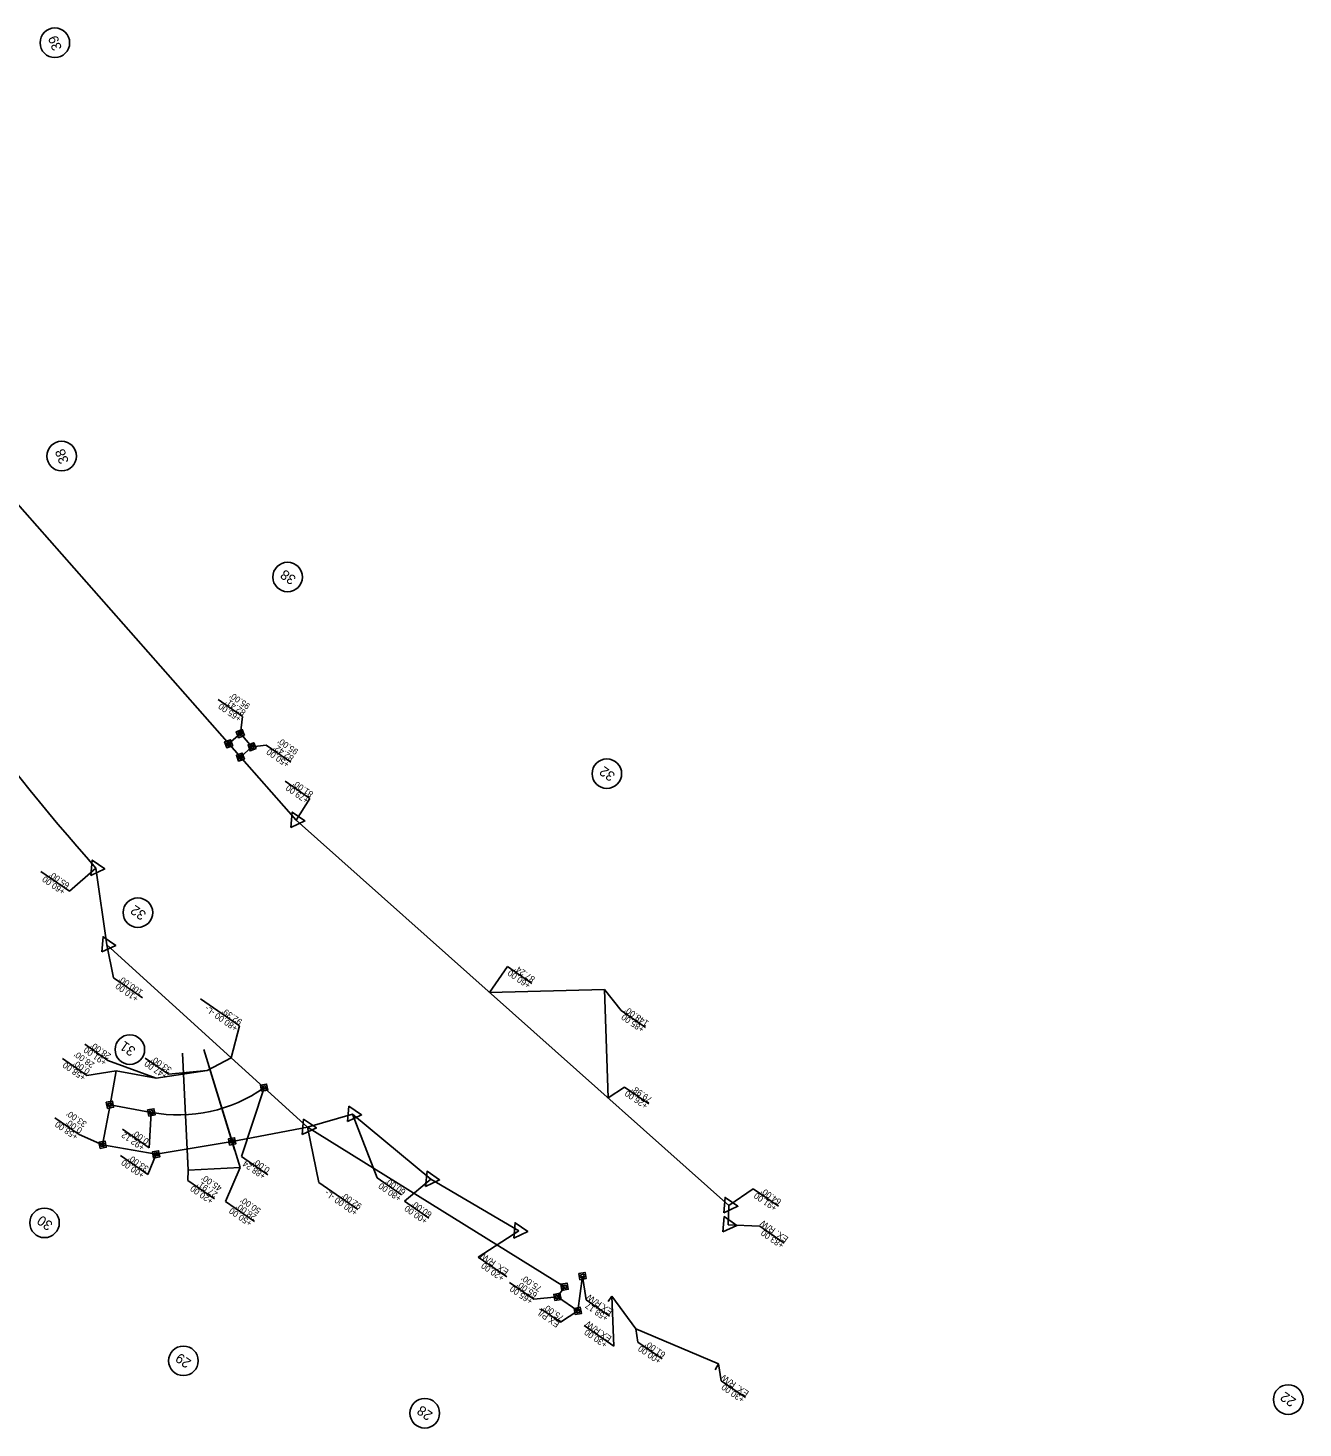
# Model space of a CAD drawing. Extents: x 474184 to 481900, y 489262 to 505659.
# Drawn here: x 478811 to 479844, y 493622 to 494757 of the extents above; entities that cross this region are included whole.
import ezdxf

# ---------------------------------------------------------------- set-up
doc = ezdxf.new("R2010")
doc.units = 0
for name, color, linetype in [('Prop Drainage Structure Drop Inlet Grate 2 Narrow Slots and Sag Grates 840 24 CELL', 7, 'Continuous'), ('Prop Drainage Structure Drop Inlet Grate 2 Wide Slots and Sag Grates 840 22 CELL', 7, 'Continuous'), ('Prop Drainage Structure Outlet Berm Ditch 850 10 CELL', 7, 'Continuous'), ('Prop Drainage Structure Outlet Berm Ditch 850 10 Label', 7, 'Continuous'), ('Prop Drainage Structure Pipe CSP 15in', 7, 'Continuous'), ('Prop Drainage Structure Pipe RCP 18in Class IV', 7, 'Continuous'), ('Prop Drainage Structure Pipe RCP 18in Class IV Label', 7, 'Continuous'), ('Prop Drainage Structure Pipe Side Drain 15in Label', 7, 'Continuous'), ('Prop Drainage Structure Pipe Stub Out CELL', 7, 'Continuous'), ('Prop Drainage Structure Plot Symbol 50 Scale', 7, 'Continuous'), ('Prop Earthen Structure Base Ditch Lateral Detail Label', 7, 'Continuous'), ('Prop Earthen Structure False Sump CELL', 7, 'Continuous'), ('Prop Earthen Structure False Sump Label', 7, 'Continuous'), ('Sheet Block Title CELL', 7, 'Continuous')]:
    doc.layers.add(name, color=color, linetype=linetype)

msp = doc.modelspace()

# ---------------------------------------------------------------- linework, layer by layer
at = {"layer": 'Prop Drainage Structure Drop Inlet Grate 2 Narrow Slots and Sag Grates 840 24 CELL'}
for p, q in [((479278, 493977.6), (479184.8, 493975.3)), ((479281, 493889.7), (479278, 493977.6))]:
    msp.add_line(p, q, dxfattribs=at)
at = {"layer": 'Prop Drainage Structure Drop Inlet Grate 2 Wide Slots and Sag Grates 840 22 CELL'}
for p, q in [((478871.1, 493851.7), (478877.2, 493884.2)), ((478877.2, 493884.2), (478910.7, 493877.9)), ((479037.3, 493866), (478976.2, 493854.4)), ((478976.2, 493854.4), (478914.6, 493844)), ((478914.6, 493844), (478871.1, 493851.7)), ((479281.1, 493724.5), (479284.1, 493729)), ((479367.7, 493669.3), (479370.6, 493674.1))]:
    msp.add_line(p, q, dxfattribs=at)
msp.add_arc((478932.7, 493995.9), 120, 259.4473, 305.3419, dxfattribs=at)
at = {"layer": 'Prop Drainage Structure Outlet Berm Ditch 850 10 CELL'}
for p, q in [((479199.4, 493996.2), (479219.1, 493982.6)), ((479291.5, 493960.6), (479311.3, 493946.9)), ((479294.4, 493898.5), (479314.1, 493884.9))]:
    msp.add_line(p, q, dxfattribs=at)
for points in [[(479184.8, 493975.3), (479199.4, 493996.2)], [(479291.5, 493960.6), (479278, 493977.6)], [(479294.4, 493898.5), (479281, 493889.7)]]:
    msp.add_lwpolyline(points, dxfattribs=at)
at = {"layer": 'Prop Drainage Structure Outlet Berm Ditch 850 10 Label'}
for p, q in [((478982.9, 494185.2), (478973.4, 494176.9)), ((478992.3, 494174.5), (478982.9, 494185.2)), ((478982.9, 494166.1), (478992.3, 494174.5)), ((479245.7, 493736.6), (479037.3, 493866)), ((479256.5, 493717), (479260.3, 493745.2)), ((479240, 493728.4), (479245.7, 493736.6)), ((479240, 493728.4), (479256.5, 493717))]:
    msp.add_line(p, q, dxfattribs=at)
at = {"layer": 'Prop Drainage Structure Pipe CSP 15in'}
for p, q in [((478832.5, 494745.5), (478832.5, 494745.5)), ((478838, 494410.3), (478838, 494410.3)), ((479021.2, 494312.2), (479021.2, 494312.2)), ((479280, 494152.7), (479280, 494152.7)), ((478899.8, 494040), (478899.8, 494040)), ((478893.3, 493928.9), (478893.3, 493928.9)), ((478824.1, 493788.4), (478824.1, 493788.4)), ((478936.7, 493676.5), (478936.7, 493676.5)), ((479832.4, 493645.1), (479832.4, 493645.1)), ((479132.4, 493634), (479132.4, 493634))]:
    msp.add_line(p, q, dxfattribs=at)
for centre in [(478832.5, 494745.5), (478838, 494410.3), (479021.2, 494312.2), (479280, 494152.7), (478899.8, 494040), (478893.3, 493928.9), (478824.1, 493788.4), (478936.7, 493676.5), (479832.4, 493645.1), (479132.4, 493634)]:
    msp.add_circle(centre, 12, dxfattribs=at)
at = {"layer": 'Prop Drainage Structure Pipe RCP 18in Class IV'}
for p, q in [((478982.9, 494185.2), (478982.9, 494185.2)), ((478973.4, 494176.9), (478973.4, 494176.9)), ((478992.3, 494174.5), (478992.3, 494174.5)), ((478982.9, 494166.1), (478982.9, 494166.1)), ((479028, 494115), (479028, 494115)), ((478865.8, 494076), (478865.8, 494076)), ((478874.6, 494014), (478874.6, 494014)), ((479002.1, 493898), (479002.1, 493898)), ((478877.2, 493884.2), (478877.2, 493884.2)), ((478910.7, 493877.9), (478910.7, 493877.9)), ((479037.3, 493866), (479037.3, 493866)), ((479073.9, 493876.5), (479073.9, 493876.5)), ((478976.2, 493854.4), (478976.2, 493854.4)), ((478871.1, 493851.7), (478871.1, 493851.7)), ((478914.6, 493844), (478914.6, 493844)), ((479137.2, 493823.8), (479137.2, 493823.8)), ((479379, 493802.5), (479379, 493802.5)), ((479378.3, 493786.9), (479378.3, 493786.9)), ((479208.7, 493782), (479208.7, 493782)), ((479260.3, 493745.2), (479260.3, 493745.2)), ((479245.7, 493736.6), (479245.7, 493736.6)), ((479240, 493728.4), (479240, 493728.4)), ((479256.5, 493717), (479256.5, 493717))]:
    msp.add_line(p, q, dxfattribs=at)
for points in [[(479023.9, 494109.1), (479024.9, 494121.5), (479035.2, 494114.4)], [(478861.7, 494070.1), (478862.8, 494082.6), (478873, 494075.4)], [(478870.5, 494008.1), (478871.6, 494020.5), (478881.8, 494013.4)], [(479069.8, 493870.5), (479070.9, 493883), (479081.1, 493875.9)], [(479033.1, 493860.1), (479034.2, 493872.5), (479044.5, 493865.4)], [(479133.1, 493817.9), (479134.2, 493830.3), (479144.4, 493823.2)], [(479374.9, 493796.6), (479375.9, 493809), (479386.2, 493801.9)], [(479204.6, 493776.1), (479205.6, 493788.5), (479215.9, 493781.4)], [(479374.1, 493781), (479375.2, 493793.5), (479385.4, 493786.3)]]:
    msp.add_lwpolyline(points, close=True, dxfattribs=at)
at = {"layer": 'Prop Drainage Structure Pipe RCP 18in Class IV Label'}
for points in [[(478986.2, 494183.7), (478981.4, 494181.9), (478979.6, 494186.7), (478984.4, 494188.5)], [(478984.5, 494184.5), (478982.1, 494183.6), (478981.3, 494186), (478983.6, 494186.9)], [(478976.7, 494175.4), (478971.9, 494173.7), (478970.1, 494178.4), (478974.9, 494180.2)], [(478975, 494176.2), (478972.7, 494175.3), (478971.8, 494177.7), (478974.2, 494178.6)], [(478995.6, 494173), (478990.8, 494171.2), (478989.1, 494176), (478993.8, 494177.8)], [(478994, 494173.7), (478991.6, 494172.8), (478990.7, 494175.2), (478993.1, 494176.1)], [(478986.2, 494164.6), (478981.4, 494162.9), (478979.7, 494167.6), (478984.4, 494169.4)], [(478984.6, 494165.4), (478982.2, 494164.5), (478981.3, 494166.9), (478983.7, 494167.8)], [(479000, 493895.1), (478999.1, 493900.1), (479004.1, 493901), (479005.1, 493896)], [(479001.1, 493896.5), (479000.6, 493899), (479003.1, 493899.5), (479003.6, 493897)], [(478875.1, 493881.2), (478874.2, 493886.2), (478879.2, 493887.1), (478880.1, 493882.1)], [(478876.1, 493882.7), (478875.7, 493885.2), (478878.2, 493885.7), (478878.6, 493883.2)], [(478908.7, 493875), (478907.7, 493880), (478912.8, 493880.9), (478913.7, 493875.9)], [(478909.7, 493876.4), (478909.2, 493879), (478911.7, 493879.4), (478912.2, 493876.9)], [(478869.1, 493848.8), (478868.2, 493853.8), (478873.2, 493854.7), (478874.1, 493849.7)], [(478974.1, 493851.5), (478973.2, 493856.5), (478978.2, 493857.4), (478979.1, 493852.4)], [(478975.1, 493852.9), (478974.7, 493855.5), (478977.2, 493855.9), (478977.6, 493853.4)], [(478870.1, 493850.3), (478869.6, 493852.8), (478872.1, 493853.2), (478872.6, 493850.7)], [(478912.5, 493841), (478911.6, 493846), (478916.6, 493846.9), (478917.5, 493841.9)], [(478913.6, 493842.5), (478913.1, 493845), (478915.6, 493845.4), (478916.1, 493842.9)], [(479258.2, 493742.3), (479257.3, 493747.3), (479262.3, 493748.2), (479263.2, 493743.2)], [(479259.2, 493743.7), (479258.8, 493746.2), (479261.3, 493746.7), (479261.7, 493744.2)], [(479237.9, 493725.4), (479237, 493730.4), (479242, 493731.3), (479242.9, 493726.3)], [(479238.9, 493726.9), (479238.5, 493729.4), (479241, 493729.8), (479241.5, 493727.3)], [(479243.6, 493733.6), (479242.7, 493738.6), (479247.7, 493739.5), (479248.7, 493734.5)], [(479244.7, 493735.1), (479244.2, 493737.6), (479246.7, 493738), (479247.2, 493735.5)], [(479254.4, 493714), (479253.5, 493719), (479258.5, 493719.9), (479259.5, 493714.9)], [(479255.5, 493715.5), (479255, 493718), (479257.5, 493718.4), (479258, 493715.9)]]:
    msp.add_lwpolyline(points, close=True, dxfattribs=at)
at = {"layer": 'Prop Drainage Structure Pipe Side Drain 15in Label'}
for p, q in [((479379, 493802.5), (479028, 494115)), ((478874.6, 494014), (478865.8, 494076)), ((479037.3, 493866), (478874.6, 494014)), ((479378.3, 493786.9), (479379, 493802.5))]:
    msp.add_line(p, q, dxfattribs=at)
for points in [[(479028, 494115), (478737.9, 494444.3)], [(479208.7, 493782), (479137.2, 493823.8), (479073.9, 493876.5), (479037.3, 493866)]]:
    msp.add_lwpolyline(points, dxfattribs=at)
msp.add_arc((480454.8, 495471.8), 2115, 200.8785, 221.2966, dxfattribs=at)
at = {"layer": 'Prop Drainage Structure Pipe Stub Out CELL'}
for p, q in [((478877.2, 493884.2), (478882.3, 493911.7)), ((478914.7, 493905.7), (478882.3, 493911.7)), ((478956.1, 493912.1), (478914.7, 493905.7)), ((478975.4, 493922.3), (478956.1, 493912.1)), ((478982.6, 493833.4), (478976.2, 493854.4)), ((478940.6, 493831.1), (478939.8, 493848.2)), ((478982.6, 493833.4), (478940.6, 493831.1)), ((479303.5, 493702.5), (479284.1, 493729)), ((479370.6, 493674.1), (479303.5, 493702.5))]:
    msp.add_line(p, q, dxfattribs=at)
at = {"layer": 'Prop Drainage Structure Plot Symbol 50 Scale'}
for p, q in [((479019.2, 494146.6), (479039.2, 494132.7)), ((479039.2, 494132.7), (479028, 494115)), ((478821.2, 494073.4), (478844.4, 494057.3)), ((478880, 493987.1), (478903.6, 493970.8)), ((479046.6, 493821.2), (479078.2, 493799.2)), ((479093.7, 493824.8), (479113.5, 493811.1)), ((479398.7, 493816.1), (479419.2, 493801.9)), ((479116, 493805.9), (479135.8, 493792.2)), ((479175.8, 493760.7), (479208.7, 493782)), ((479403.9, 493785.7), (479423.7, 493772)), ((479175.8, 493760.7), (479199, 493744.6))]:
    msp.add_line(p, q, dxfattribs=at)
for points in [[(478844.4, 494057.3), (478865.8, 494076)], [(478880, 493987.1), (478874.6, 494014)], [(479046.6, 493821.2), (479037.3, 493866)], [(479093.7, 493824.8), (479073.9, 493876.5)], [(479116, 493805.9), (479137.2, 493823.8)], [(479398.7, 493816.1), (479379, 493802.5)], [(479403.9, 493785.7), (479378.3, 493786.9)]]:
    msp.add_lwpolyline(points, dxfattribs=at)
at = {"layer": 'Prop Earthen Structure Base Ditch Lateral Detail Label'}
for p, q in [((478964.9, 494212.8), (478984.7, 494199.1)), ((478984.7, 494199.1), (478982.9, 494185.2)), ((479003.9, 494175.8), (478992.3, 494174.5)), ((479003.9, 494175.8), (479023.7, 494162.1)), ((479201.1, 493740.1), (479220.9, 493726.4)), ((479226.6, 493718.8), (479242.5, 493707.8)), ((479263.2, 493725.9), (479282.1, 493712.8))]:
    msp.add_line(p, q, dxfattribs=at)
for points in [[(479263.2, 493725.9), (479260.3, 493745.2)], [(479220.9, 493726.4), (479240, 493728.4)], [(479242.5, 493707.8), (479256.5, 493717)]]:
    msp.add_lwpolyline(points, dxfattribs=at)
at = {"layer": 'Prop Earthen Structure False Sump CELL'}
for p, q in [((478832.4, 493873.7), (478852.1, 493860)), ((478887.2, 493864.3), (478908.9, 493849.2)), ((478885.7, 493843.1), (478908, 493827.6)), ((478908, 493827.6), (478914.6, 493844)), ((478983.7, 493842.1), (479005.1, 493827.3))]:
    msp.add_line(p, q, dxfattribs=at)
for points in [[(478983.7, 493842.1), (479002.1, 493898)], [(478908.9, 493849.2), (478910.7, 493877.9)], [(478852.1, 493860), (478871.1, 493851.7)]]:
    msp.add_lwpolyline(points, dxfattribs=at)
at = {"layer": 'Prop Earthen Structure False Sump Label'}
for p, q in [((478950.5, 493970.1), (478982.1, 493948.1)), ((478856.7, 493933.2), (478875.5, 493920.1)), ((478838.6, 493921.6), (478858.3, 493907.9)), ((478905.8, 493922.1), (478924.6, 493909)), ((478940.6, 493831.1), (478940.3, 493822.7)), ((478940.3, 493822.7), (478961.8, 493807.8)), ((478970.9, 493805.6), (478994.3, 493789.4)), ((479285.6, 493688.5), (479284.1, 493729)), ((479261.5, 493705.2), (479285.6, 493688.5)), ((479305.1, 493691.7), (479324.8, 493678)), ((479372.7, 493660.4), (479392.5, 493646.7))]:
    msp.add_line(p, q, dxfattribs=at)
for points in [[(478982.1, 493948.1), (478975.4, 493922.3)], [(478858.3, 493907.9), (478882.3, 493911.7)], [(478875.5, 493920.1), (478914.7, 493905.7)], [(478924.6, 493909), (478956.1, 493912.1)], [(478970.9, 493805.6), (478982.6, 493833.4)], [(479305.1, 493691.7), (479303.5, 493702.5)], [(479372.7, 493660.4), (479370.6, 493674.1)]]:
    msp.add_lwpolyline(points, dxfattribs=at)
at = {"layer": 'Sheet Block Title CELL'}
for p, q in [((478936, 493926), (478940.6, 493831.1)), ((478953.2, 493929), (478982.6, 493833.4)), ((478957.6, 493914.6), (478978.2, 493847.7))]:
    msp.add_line(p, q, dxfattribs=at)

# ---------------------------------------------------------------- texts
at = {"layer": 'Prop Drainage Structure Outlet Berm Ditch 850 10 CELL'}
for s, p in [('+60.00', (479218.7, 493982.1)), ("87.24'", (479222.3, 493987.2)), ('+85.00', (479310.9, 493946.4)), ("148.00'", (479314.5, 493951.5)), ('+26.00', (479313.7, 493884.4)), ("79.98' ", (479317.3, 493889.5))]:
    msp.add_text(s, height=5, rotation=145.2516, dxfattribs=at).set_placement(p)
at = {"layer": 'Prop Drainage Structure Pipe CSP 15in'}
for s, rotation, p in [('39', 110.469, (478838.4, 494741)), ('38', 110.469, (478844, 494405.8)), ('38', 145.2516, (479028.7, 494311.9)), ('32', 145.2516, (479287.4, 494152.4)), ('32', 145.2516, (478907.2, 494039.8)), ('31', 145.2516, (478898.7, 493929.5)), ('30', 145.2516, (478831.5, 493788.1)), ('29', 145.2516, (478943.7, 493676.5)), ('22', 145.2516, (479839.4, 493645.1)), ('28', 145.2516, (479139.5, 493634))]:
    msp.add_text(s, height=8, rotation=rotation, dxfattribs=at).set_placement(p)
at = {"layer": 'Prop Drainage Structure Plot Symbol 50 Scale'}
for s, p in [('+79.00', (479038.9, 494132.2)), ("81.00'", (479042.5, 494137.3)), ("65.00'", (478845, 494063.3)), ('+60.00', (478841.4, 494058.2)), ('+10.00', (478900.8, 493971.4)), ("100.00'", (478904.4, 493976.5)), ('+80.00', (479114, 493809.4)), ("60.00'", (479117.5, 493814.6)), ('+00.00 -L-', (479078.4, 493797.9)), ("92.00'", (479081.9, 493803)), ('+91.00', (479418.4, 493801.5)), ("64.00'", (479422, 493806.7)), ('+00.00', (479135.1, 493791.1)), ("60.00'", (479138.7, 493796.3)), ('EX. R/W', (479427.6, 493776.4)), ('+83.00', (479424.1, 493771.3)), ('EX. R/W', (479200.9, 493749.9)), ('+20.00', (479197.3, 493744.7))]:
    msp.add_text(s, height=5, rotation=145.2516, dxfattribs=at).set_placement(p)
at = {"layer": 'Prop Earthen Structure Base Ditch Lateral Detail Label'}
for s, p in [('+65.00', (478984.2, 494198.4)), ("82.41'", (478987.8, 494203.5)), ("95.00'", (478991.3, 494208.6)), ('+50.00', (479023.2, 494161.4)), ("82.42'", (479026.8, 494166.5)), ("95.00'", (479030.3, 494171.7)), ("75.00'", (479227.7, 493736.1)), ('+65.00', (479220.5, 493725.9)), ("65.00'", (479224.1, 493731)), ('EX.R/W', (479285.3, 493717.5)), ('EX.P/L', (479242.1, 493707.2)), ("75.00'", (479245.7, 493712.4)), ('+58.17', (479281.7, 493712.3))]:
    msp.add_text(s, height=5, rotation=145.2516, dxfattribs=at).set_placement(p)
at = {"layer": 'Prop Earthen Structure False Sump CELL'}
for s, p in [("33.00'", (478858.9, 493869.7)), ('+58.00', (478851.8, 493859.4)), ("0.00'", (478855.3, 493864.6)), ('+92.12', (478905.7, 493850.7)), ("0.00'", (478909.3, 493855.8)), ('+00.00', (478905.5, 493828.3)), ("33.00'", (478909.1, 493833.4)), ('+88.24', (479003.9, 493827.4)), ("0.00'", (479007.4, 493832.5))]:
    msp.add_text(s, height=5, rotation=145.2516, dxfattribs=at).set_placement(p)
at = {"layer": 'Prop Earthen Structure False Sump Label'}
for s, p in [('+80.00 -L-', (478981.3, 493947.4)), ("92.39'", (478984.9, 493952.6)), ("28.00'", (478878.5, 493924.9)), ("28.00'", (478865.1, 493917.7)), ('+91.00', (478875, 493919.7)), ("33.00'", (478927.8, 493913.6)), ('+58.00', (478858, 493907.4)), ("0.00'", (478861.5, 493912.5)), ('+47.00', (478924.3, 493908.5)), ("27.91'", (478965, 493812.5)), ("45.00'", (478968.5, 493817.6)), ('+20.00', (478961.4, 493807.3)), ('+50.00', (478992.9, 493789.2)), ("28.00'", (478996.5, 493794.3)), ("50.00'", (479000, 493799.4)), ('EX.R/W', (479284.4, 493695.8)), ('+30.00', (479280.9, 493690.7)), ('+00.00', (479324.5, 493677.5)), ("61.00'", (479328.1, 493682.6)), ('EX. R/W', (479395.7, 493651.3)), ('+30.00', (479392.1, 493646.2))]:
    msp.add_text(s, height=5, rotation=145.2516, dxfattribs=at).set_placement(p)

doc.saveas('drawing.dxf')
